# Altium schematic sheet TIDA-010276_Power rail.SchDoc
size 431 x 279 mm; Date: Not shown in title block; ApprovedBy: Not shown in title block; CheckedBy: Not shown in title block; Author: Not shown in title block; CompanyName: Not shown in title block; DrawnBy: Jenson Fang; Engineer: Jenson Fang; Organization: Not shown in title block; Address1: Not shown in title block; Address2: Not shown in title block; Address3: Not shown in title block; Address4: Not shown in title block; DocumentNumber: 1; Revision: Use project parameter SCH_Rev; SheetNumber: 3; SheetTotal: 6; PageSetup: Record=PageOptions¦CenterHorizontal=True¦CenterVertical=True¦PrintScale=1.00¦XCorrection=1.00¦YCorrection=1.00¦PrintKind=0¦BorderSize=5000000¦LeftOffset=0¦BottomOffset=0¦Orientation=2¦PaperLength=1000¦PaperWidth=1000¦Scale=100¦PaperSource=15¦PrintQuality=600¦MediaType=1¦DitherType=10¦PaperKind=Letter¦PrintScaleMode=1
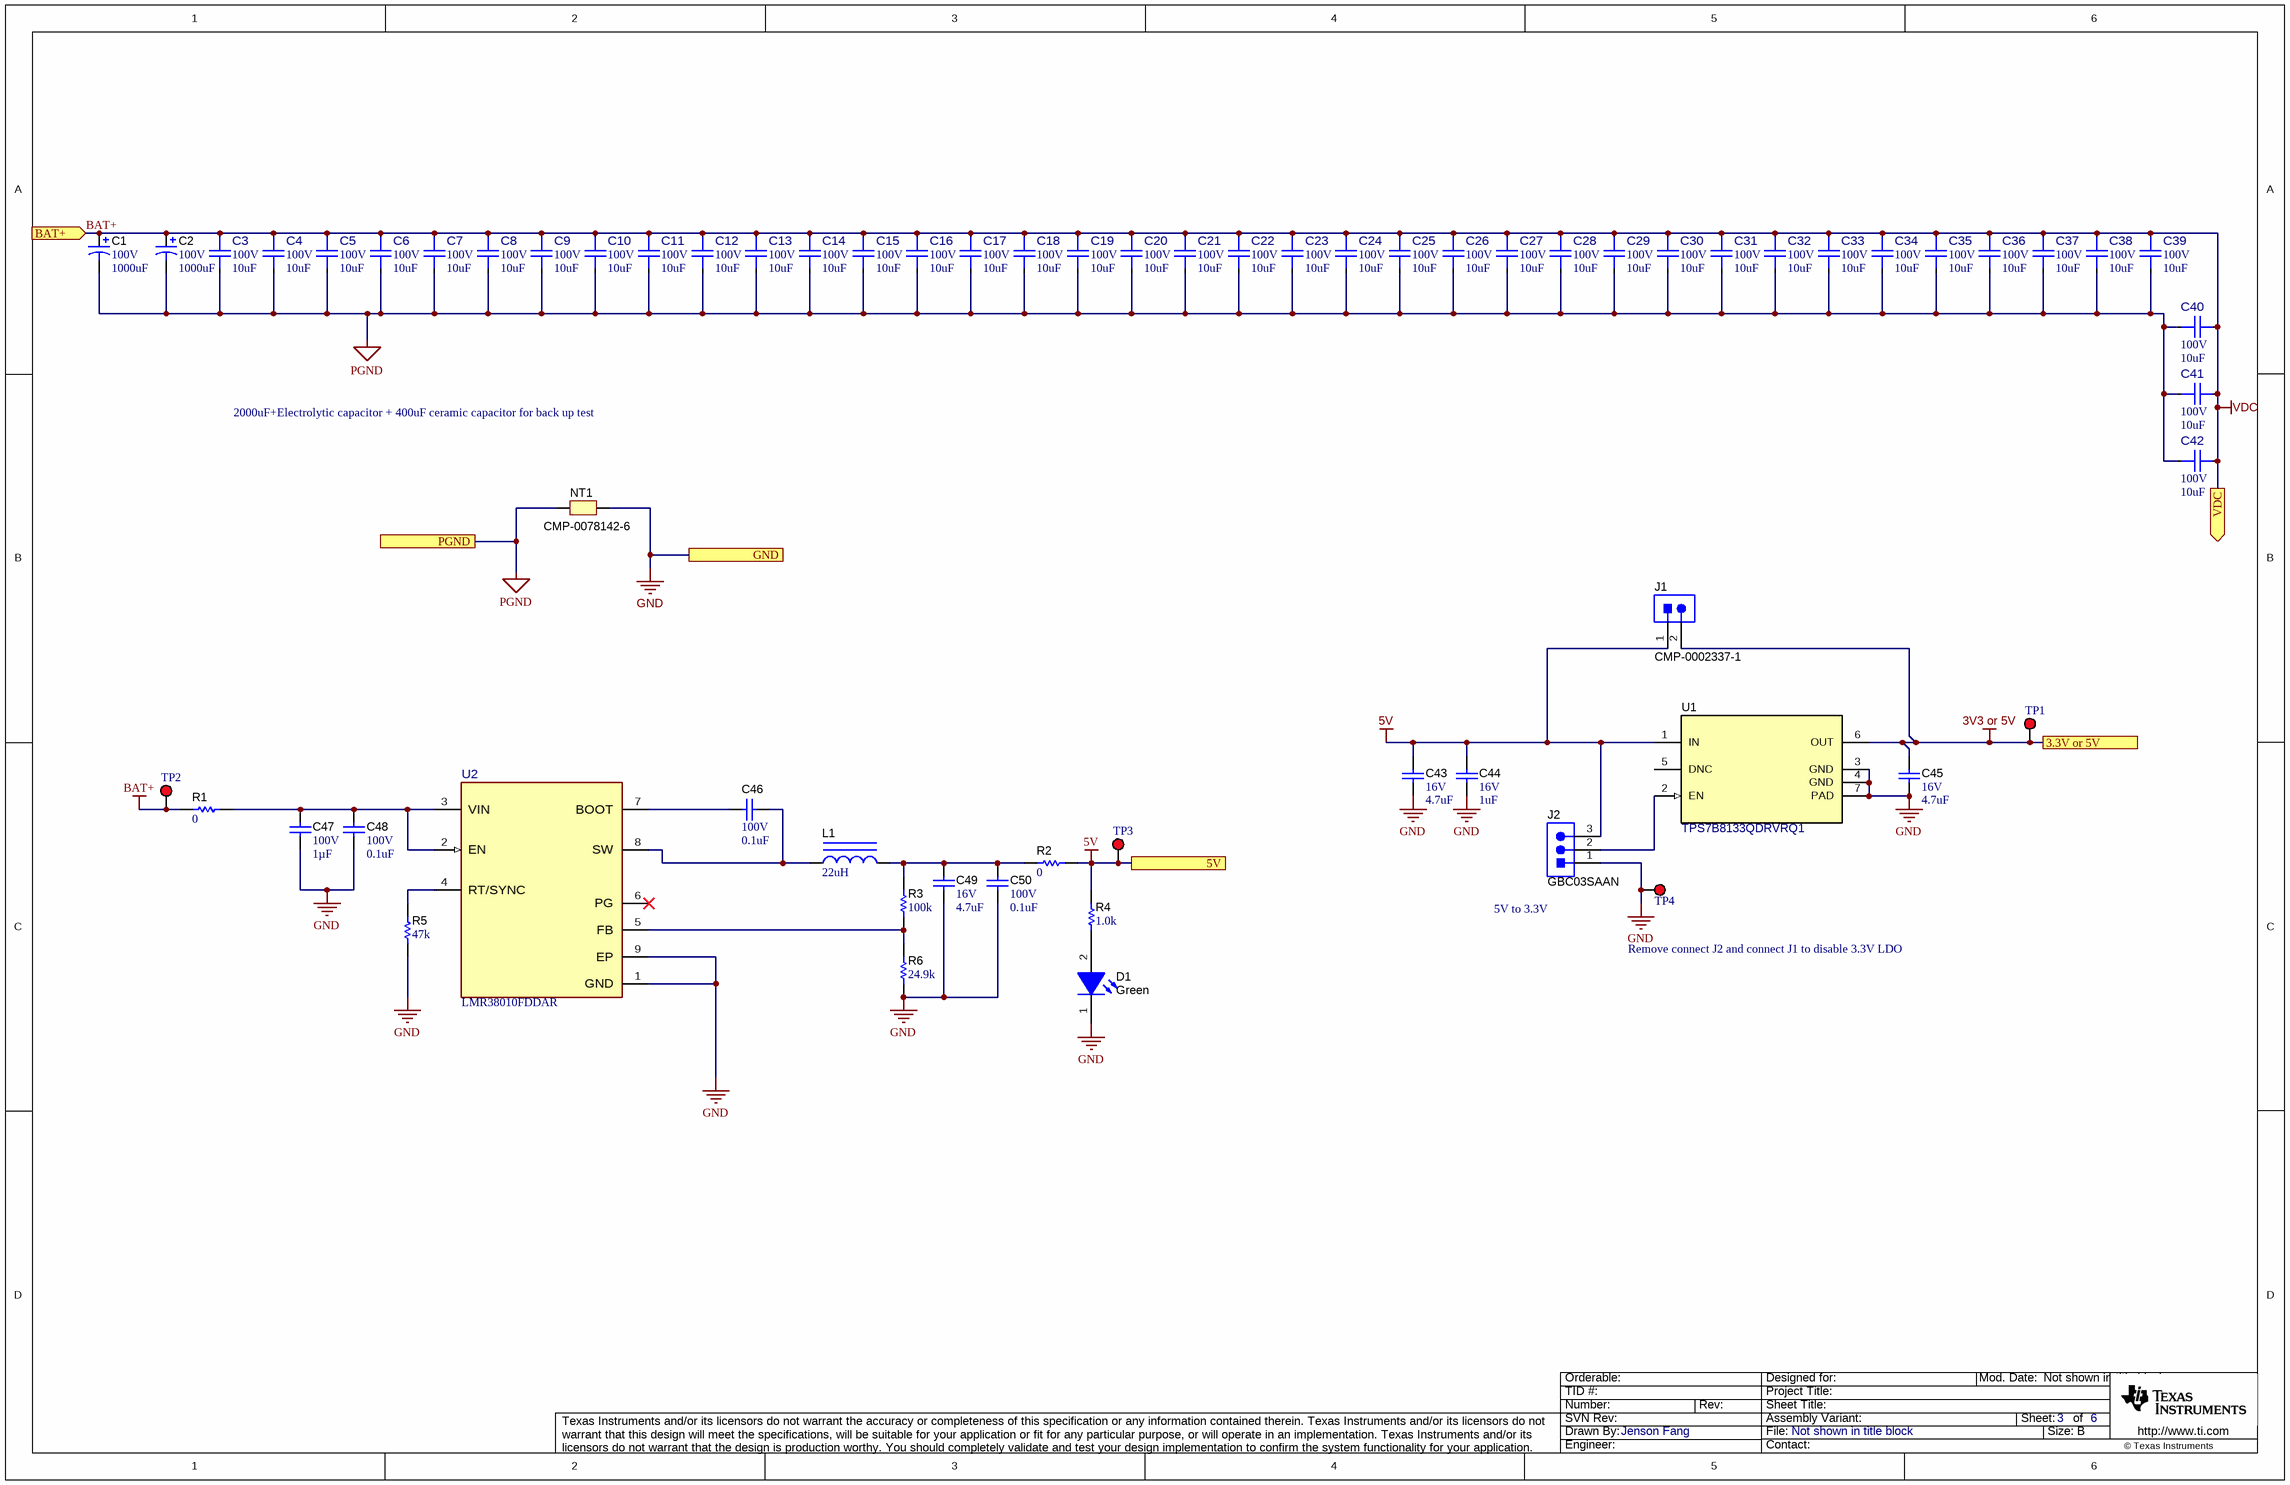
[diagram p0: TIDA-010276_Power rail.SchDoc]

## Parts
C1  VDC_V: 100V  ValueDisplayed: 1000uF  [M_1800x3550]  (hidden comment: ECA-2AM102)
C2  VDC_V: 100V  ValueDisplayed: 1000uF  [M_1800x3550]  (hidden comment: ECA-2AM102)
C3  VDC_V: 100V  ValueDisplayed: 10uF  [FP-C3225X7R2A106K250AC_1210-MFG]  (hidden comment: C3225X7R2A106K250AC)
C4  VDC_V: 100V  ValueDisplayed: 10uF  [FP-C3225X7R2A106K250AC_1210-MFG]  (hidden comment: C3225X7R2A106K250AC)
C5  VDC_V: 100V  ValueDisplayed: 10uF  [FP-C3225X7R2A106K250AC_1210-MFG]  (hidden comment: C3225X7R2A106K250AC)
C6  VDC_V: 100V  ValueDisplayed: 10uF  [FP-C3225X7R2A106K250AC_1210-MFG]  (hidden comment: C3225X7R2A106K250AC)
C7  VDC_V: 100V  ValueDisplayed: 10uF  [FP-C3225X7R2A106K250AC_1210-MFG]  (hidden comment: C3225X7R2A106K250AC)
C8  VDC_V: 100V  ValueDisplayed: 10uF  [FP-C3225X7R2A106K250AC_1210-MFG]  (hidden comment: C3225X7R2A106K250AC)
C9  VDC_V: 100V  ValueDisplayed: 10uF  [FP-C3225X7R2A106K250AC_1210-MFG]  (hidden comment: C3225X7R2A106K250AC)
C10  VDC_V: 100V  ValueDisplayed: 10uF  [FP-C3225X7R2A106K250AC_1210-MFG]  (hidden comment: C3225X7R2A106K250AC)
C11  VDC_V: 100V  ValueDisplayed: 10uF  [FP-C3225X7R2A106K250AC_1210-MFG]  (hidden comment: C3225X7R2A106K250AC)
C12  VDC_V: 100V  ValueDisplayed: 10uF  [FP-C3225X7R2A106K250AC_1210-MFG]  (hidden comment: C3225X7R2A106K250AC)
C13  VDC_V: 100V  ValueDisplayed: 10uF  [FP-C3225X7R2A106K250AC_1210-MFG]  (hidden comment: C3225X7R2A106K250AC)
C14  VDC_V: 100V  ValueDisplayed: 10uF  [FP-C3225X7R2A106K250AC_1210-MFG]  (hidden comment: C3225X7R2A106K250AC)
C15  VDC_V: 100V  ValueDisplayed: 10uF  [FP-C3225X7R2A106K250AC_1210-MFG]  (hidden comment: C3225X7R2A106K250AC)
C16  VDC_V: 100V  ValueDisplayed: 10uF  [FP-C3225X7R2A106K250AC_1210-MFG]  (hidden comment: C3225X7R2A106K250AC)
C17  VDC_V: 100V  ValueDisplayed: 10uF  [FP-C3225X7R2A106K250AC_1210-MFG]  (hidden comment: C3225X7R2A106K250AC)
C18  VDC_V: 100V  ValueDisplayed: 10uF  [FP-C3225X7R2A106K250AC_1210-MFG]  (hidden comment: C3225X7R2A106K250AC)
C19  VDC_V: 100V  ValueDisplayed: 10uF  [FP-C3225X7R2A106K250AC_1210-MFG]  (hidden comment: C3225X7R2A106K250AC)
C20  VDC_V: 100V  ValueDisplayed: 10uF  [FP-C3225X7R2A106K250AC_1210-MFG]  (hidden comment: C3225X7R2A106K250AC)
C21  VDC_V: 100V  ValueDisplayed: 10uF  [FP-C3225X7R2A106K250AC_1210-MFG]  (hidden comment: C3225X7R2A106K250AC)
C22  VDC_V: 100V  ValueDisplayed: 10uF  [FP-C3225X7R2A106K250AC_1210-MFG]  (hidden comment: C3225X7R2A106K250AC)
C23  VDC_V: 100V  ValueDisplayed: 10uF  [FP-C3225X7R2A106K250AC_1210-MFG]  (hidden comment: C3225X7R2A106K250AC)
C24  VDC_V: 100V  ValueDisplayed: 10uF  [FP-C3225X7R2A106K250AC_1210-MFG]  (hidden comment: C3225X7R2A106K250AC)
C25  VDC_V: 100V  ValueDisplayed: 10uF  [FP-C3225X7R2A106K250AC_1210-MFG]  (hidden comment: C3225X7R2A106K250AC)
C26  VDC_V: 100V  ValueDisplayed: 10uF  [FP-C3225X7R2A106K250AC_1210-MFG]  (hidden comment: C3225X7R2A106K250AC)
C27  VDC_V: 100V  ValueDisplayed: 10uF  [FP-C3225X7R2A106K250AC_1210-MFG]  (hidden comment: C3225X7R2A106K250AC)
C28  VDC_V: 100V  ValueDisplayed: 10uF  [FP-C3225X7R2A106K250AC_1210-MFG]  (hidden comment: C3225X7R2A106K250AC)
C29  VDC_V: 100V  ValueDisplayed: 10uF  [FP-C3225X7R2A106K250AC_1210-MFG]  (hidden comment: C3225X7R2A106K250AC)
C30  VDC_V: 100V  ValueDisplayed: 10uF  [FP-C3225X7R2A106K250AC_1210-MFG]  (hidden comment: C3225X7R2A106K250AC)
C31  VDC_V: 100V  ValueDisplayed: 10uF  [FP-C3225X7R2A106K250AC_1210-MFG]  (hidden comment: C3225X7R2A106K250AC)
C32  VDC_V: 100V  ValueDisplayed: 10uF  [FP-C3225X7R2A106K250AC_1210-MFG]  (hidden comment: C3225X7R2A106K250AC)
C33  VDC_V: 100V  ValueDisplayed: 10uF  [FP-C3225X7R2A106K250AC_1210-MFG]  (hidden comment: C3225X7R2A106K250AC)
C34  VDC_V: 100V  ValueDisplayed: 10uF  [FP-C3225X7R2A106K250AC_1210-MFG]  (hidden comment: C3225X7R2A106K250AC)
C35  VDC_V: 100V  ValueDisplayed: 10uF  [FP-C3225X7R2A106K250AC_1210-MFG]  (hidden comment: C3225X7R2A106K250AC)
C36  VDC_V: 100V  ValueDisplayed: 10uF  [FP-C3225X7R2A106K250AC_1210-MFG]  (hidden comment: C3225X7R2A106K250AC)
C37  VDC_V: 100V  ValueDisplayed: 10uF  [FP-C3225X7R2A106K250AC_1210-MFG]  (hidden comment: C3225X7R2A106K250AC)
C38  VDC_V: 100V  ValueDisplayed: 10uF  [FP-C3225X7R2A106K250AC_1210-MFG]  (hidden comment: C3225X7R2A106K250AC)
C39  VDC_V: 100V  ValueDisplayed: 10uF  [FP-C3225X7R2A106K250AC_1210-MFG]  (hidden comment: C3225X7R2A106K250AC)
C40  VDC_V: 100V  ValueDisplayed: 10uF  [FP-C3225X7R2A106K250AC_1210-MFG]  (hidden comment: C3225X7R2A106K250AC)
C41  VDC_V: 100V  ValueDisplayed: 10uF  [FP-C3225X7R2A106K250AC_1210-MFG]  (hidden comment: C3225X7R2A106K250AC)
C42  VDC_V: 100V  ValueDisplayed: 10uF  [FP-C3225X7R2A106K250AC_1210-MFG]  (hidden comment: C3225X7R2A106K250AC)
C43  VDC_V: 16V  ValueDisplayed: 4.7uF  [0603]  (hidden comment: C1608X6S1C475K080AC)
C44  VDC_V: 16V  ValueDisplayed: 1uF  [0603]  (hidden comment: GRM185R61C105KE44D)
C45  VDC_V: 16V  ValueDisplayed: 4.7uF  [0603]  (hidden comment: C1608X6S1C475K080AC)
C46  VDC_V: 100V  ValueDisplayed: 0.1uF  [0402]  (hidden comment: GRM155R62A104KE14D)
C47  VDC_V: 100V  ValueDisplayed: 1µF  [0805_HV]  (hidden comment: C2012X7S2A105K125AE)
C48  VDC_V: 100V  ValueDisplayed: 0.1uF  [0402]  (hidden comment: GRM155R62A104KE14D)
C49  VDC_V: 16V  ValueDisplayed: 4.7uF  [0603]  (hidden comment: C1608X6S1C475K080AC)
C50  VDC_V: 100V  ValueDisplayed: 0.1uF  [0402]  (hidden comment: GRM155R62A104KE14D)
D1  value Green  [WL-SMCW_GREEN]  (hidden comment: CMP-0002905-2)
J1  CMP-0002337-1  [CONN_PEC02SAAN]
J2  GBC03SAAN  [Sullins_Gxx03SAAN]
L1  ValueDisplayed: 22uH  [WE-LHMI_4020]  (hidden comment: 74437324220)
NT1  CMP-0078142-6  [Net-Tie_50milWide_30milLong]  (net tie, no BOM)
R1  ValueDisplayed: 0  [0603]  (hidden comment: PMR03EZPJ000)
R2  ValueDisplayed: 0  [0603]  (hidden comment: PMR03EZPJ000)
R3  ValueDisplayed: 100k  [0603]  (hidden comment: CRCW0603100KJNEAC)
R4  ValueDisplayed: 1.0k  [0603]  (hidden comment: RC0603JR-071KL)
R5  ValueDisplayed: 47k  [0603]  (hidden comment: RC0603JR-0747KL)
R6  ValueDisplayed: 24.9k  [0603]  (hidden comment: RC0603FR-0724K9L)
TP1  5000  [Keystone5000]  (value not drawn)
TP2  5000  [Keystone5000]  (value not drawn)
TP3  5000  [Keystone5000]  (value not drawn)
TP4  5000  [Keystone5000]  (value not drawn)
U1  TPS7B8133QDRVRQ1  [DRV0006A]
U2  LMR38010FDDAR  [DDA0008E-MFG]

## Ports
3.3V or 5V, 5V, BAT+ (in), GND, PGND, VDC (out)

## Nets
3V3 or 5V: C45.1 J1.2 TP1.1 U1.6(OUT) ; port 3.3V or 5V
5V: C43.1 C44.1 J1.1 J2.3 R2.1 R4.2 TP3.1 U1.1(IN) ; port 5V
BAT+: C1.1(+) C2.1(+) C3.1 C4.1 C5.1 C6.1 C7.1 C8.1 C9.1 C10.1 C11.1 C12.1 C13.1 C14.1 C15.1 C16.1 C17.1 C18.1 C19.1 C20.1 C21.1 C22.1 C23.1 C24.1 C25.1 C26.1 C27.1 C28.1 C29.1 C30.1 C31.1 C32.1 C33.1 C34.1 C35.1 C36.1 C37.1 C38.1 C39.1 C40.2 C41.2 C42.2 R1.2 TP2.1 ; port BAT+, port VDC  [also labelled VDC]
GND: C43.2 C44.2 C45.2 C47.2 C48.2 C49.2 C50.2 D1.1(K) J2.1 NT1.2 R5.1 R6.1 TP4.1 U1.3(GND) U1.4(GND) U1.7(PAD) U2.1(GND) U2.9(EP) ; port GND
PGND: C1.2(-) C2.2(-) C3.2 C4.2 C5.2 C6.2 C7.2 C8.2 C9.2 C10.2 C11.2 C12.2 C13.2 C14.2 C15.2 C16.2 C17.2 C18.2 C19.2 C20.2 C21.2 C22.2 C23.2 C24.2 C25.2 C26.2 C27.2 C28.2 C29.2 C30.2 C31.2 C32.2 C33.2 C34.2 C35.2 C36.2 C37.2 C38.2 C39.2 C40.1 C41.1 C42.1 NT1.1 ; port PGND
NetC46_1: C46.1 U2.7(BOOT)
NetC46_2: C46.2 L1.1 U2.8(SW)
NetC47_1: C47.1 C48.1 R1.1 U2.2(EN) U2.3(VIN)
NetC49_1: C49.1 C50.1 L1.2 R2.2 R3.2
NetD1_2: D1.2(A) R4.1
NetJ2_2: J2.2 U1.2(EN)
NetR3_1: R3.1 R6.2 U2.5(FB)
NetR5_2: R5.2 U2.4(RT/SYNC)

Not connected (* = marked no-connect by the designer): U1 5(DNC); U2 6(PG)*

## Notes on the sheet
- 2000uF+Electrolytic capacitor + 400uF ceramic capacitor for back up test
- (near J2) 5V to 3.3V
- Remove connect J2 and connect J1 to disable 3.3V LDO

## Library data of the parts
C1 C2 = CMP-0009842-2: CAP, AL, 1000 uF, 100 V, +/- 20%, TH; Manufacturer: Panasonic; TaMin_C: -40°C; Polarized: Y; SizeAreaWB_mm2: 400; Value1: Unknown; U/M: EA; Value: 1000uF; TaMax_C: 85°C; SizeZ_mm: 37.5; SizeX_mm: 18; Cap_Case: 18x35.5mm; SizeArea_mm2: 324; CompType: Capacitor; AEC Qualified: N; Cap_F: 1mF; IRMS_A: 1.3A; AEC Category: Q200
C3-C42 = CMP-0096021-1: 10 µF ±10% 100V Ceramic Capacitor X7R 1210 (3225 Metric); Manufacturer: TDK; Cap_F: 10µF; AEC Qualified: No; Value: 10µF; SizeZ_mm: 2.85mm; TempCo: 15%
C43 C45 C49 = CMP-0007028-4: CAP, CERM, 4.7 uF, 16 V, +/- 10%, X6S, 0603; Manufacturer: TDK; TaMin_C: -55°C; ESR_ohm: 3.728m; Polarized: N; SizeAreaWB_mm2: 4.68; Value1: 0.003728 ohm; U/M: EA; Value: 4.7uF; TaMax_C: 105°C; SizeZ_mm: 1; SizeX_mm: 1.6; SizeY_mm: 0.8; SizeArea_mm2: 1.28; Cap_F: 4.7µF; IRMS_A: 2.6936A; AEC Category: Q200
C44 = CMP-0007157-5: CAP, CERM, 1 uF, 16 V, +/- 10%, X5R, 0603; Manufacturer: MuRata; TaMin_C: -55°C; Polarized: N; SizeAreaWB_mm2: 4.68; Value1: Unknown; U/M: EA; Value: 1uF; TaMax_C: 85°C; SizeZ_mm: 1; SizeX_mm: 1.6; SizeY_mm: 0.8; SizeArea_mm2: 1.28; Cap_F: 1µF; AEC Category: Q200
C46 C48 C50 = CMP-0006618-1: CAP, CERM, 0.1 uF, 100 V, +/- 10%, X5R, 0402; Manufacturer: MuRata; TaMin_C: -55°C; Polarized: N; SizeAreaWB_mm2: 3; Value1: Unknown; U/M: EA; Value: 0.1uF; TaMax_C: 85°C; SizeZ_mm: 0.6; SizeX_mm: 1; SizeY_mm: 0.5; Cap_F: 100nF; AEC Category: Q200
C47 = CMP-0750059-1: CAP, CERM, 1 µF, 100 V,+/- 10%, X7S, 0805; Manufacturer: TDK; TaMax_C: 125°C; SizeAreaWB_mm2: 6.75; SizeY_mm: 1.25; Green_REACh: Incomplete; TaMin_C: -55°C; Cap_Case: 0805; SizeZ_mm: 1.45; U/M: EA; SizeX_mm: 2; Polarized: N; Green_Lifecycle: Active; SizeArea_mm2: 2.5; Value: 1uF; AEC Category: Q200
D1 = CMP-0002905-2: LED, Green, SMD; Manufacturer: Wurth Elektronik; PartNumber: 150060GS75000; Type: InGaN; Vf_V: 3.2V; Io_A: 20mA; Tjmax_C: 85°C; Value1: W; Angle: 140
J1 = CMP-0002337-1: Header, 100mil, 2x1, Tin, TH; PartNumber: PEC02SAAN; Manufacturer: Sullins Connector Solutions; Pitch_mm: 2.54; Gender: Male; Shrouded: N; Row_Count: 1; Current_A: 3A; Voltage_V: 1.8kV; Cert_UL: Y; CNHeader: TRUE; Green_Lifecycle: Not Set; Green_REACh: Incomplete; CT: FALSE
J2 = CMP-0054577-1: Header, 2.54 mm, 3x1, Gold, TH; Manufacturer: Sullins Connector Solutions; CT: FALSE; CNHeader: TRUE
L1 = CMP-0064489-2: Inductor, Shielded Drum Core, Powdered Iron, 22 uH, 1 A, 0.47 ohm, SMD; Manufacturer: Wurth Elektronik; Isat: 2A @ 20% inductance drop; Irms: 1A @ 40C rise; Green_Lifecycle: Active; SizeAreaWB_mm2: 27.577; DCR_ohm: 0.47; Green_REACh: Passed; Value: 22uH; Imax_A: 1A; SizeZ_mm: 2; SizeX_mm: 4.45; SizeY_mm: 4.06; SizeArea_mm2: 18.067; Ind_H: 22µH; AEC Category: Q200
NT1 = CMP-0078142-6: Single point connection between nets.
R1 R2 = CMP-0086358-1: RES, 0, 0%, 0.25 W, AEC-Q200 Grade 0, 0603; Manufacturer: Rohm; Power_W: 250mW; SizeZ_mm: 1; SizeArea_mm2: 1.28; Value2: 0.25W; SizeAreaWB_mm2: 4.68; Value_Code: 0000; Value: 0; AEC Qualified: Y; AEC Category: Q200; SizeX_mm: 1.6; SizeY_mm: 0.8
R3 = CMP-0082530-1: RES, 100 k, 5%, 0.1 W, 0603; Manufacturer: Vishay-Dale; Power_W: 100mW; TempCo: 200 ppm/C; SizeAreaWB_mm2: 4.68; Value: 100k; EIA_Code: E24; SizeX_mm: 1.6; SizeY_mm: 0.8; SizeZ_mm: 1; Value2: 0.1W; SizeArea_mm2: 1.28; AEC Qualified: N; VDC_V: 75V; AEC Category: Q200
R4 = CMP-0025899-5: RES, 1.0 k, 5%, 0.1 W, 0603; Manufacturer: Yageo; Power_W: 100mW; TempCo: 100 ppm/C; Value_Code: 1k00; Value: 1.0k; EIA_Code: E24; Res_ohm: 1k; SizeX_mm: 1.6; SizeY_mm: 0.8; SizeZ_mm: 1; Value2: 0.1W; SizeArea_mm2: 1.28; AEC Qualified: N; VDC_V: 75V; AEC Category: Q200; SizeAreaWB_mm2: 4.68
R5 = CMP-0025925-5: RES, 47 k, 5%, 0.1 W, 0603; Manufacturer: Yageo; Power_W: 100mW; TempCo: 100 ppm/C; Value_Code: 47k0; Value: 47k; EIA_Code: E24; SizeX_mm: 1.6; SizeY_mm: 0.8; SizeZ_mm: 1; Value2: 0.1W; SizeArea_mm2: 1.28; AEC Qualified: N; VDC_V: 75V; AEC Category: Q200; SizeAreaWB_mm2: 4.68
R6 = CMP-0022944-5: RES, 24.9 k, 1%, 0.1 W, 0603; Manufacturer: Yageo; Power_W: 100mW; TempCo: 100 ppm/C; Value_Code: 24k9; Value: 24.9k; EIA_Code: E96; SizeX_mm: 1.6; SizeY_mm: 0.8; SizeZ_mm: 1; Value2: 0.1W; SizeArea_mm2: 1.28; AEC Qualified: N; VDC_V: 75V; AEC Category: Q200; SizeAreaWB_mm2: 4.68
TP1-TP4 = CMP-0055137-1: Test Point, Miniature, Red, TH; Manufacturer: Keystone; CNHeader: FALSE; Green_Lifecycle: Active; Green_REACh: Passed; ContactFinish: Silver; CT: TRUE
U1 = CMP-0860463-2: Automotive 150-mA high-voltage ultra-low-IQ low-dropout (LDO) linear regulator, DRV0006A (WSON-6); Alternate Manufacturer: Texas Instruments; AEC Qualified: Y; SizeY_mm: 2; SizeZ_mm: 0.8; AEC Category: Q200; CompType: IC; SizeArea_mm2: 4; SizeAreaWB_mm2: 9
U2 = CMP-0096892-1: 4.2-V to 80-V, 1-A Synchronous Buck Converter with 40-µA IQ; Manufacturer: Texas Instruments; Output Type: AdjustableProgrammable; AEC Qualified: No; Output Voltage: 1-75V; Standoff Height: 0mm; Nominal Supply Current: 40uA; Number Of Outputs: 1; TJmax_C: +150°C; Switching Frequency: 200-2200kHz; Min Supply Voltage: 4.2V; Max Duty Cycle: 97%; Max Supply Voltage: 80V; SizeZ_mm: 1.7mm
